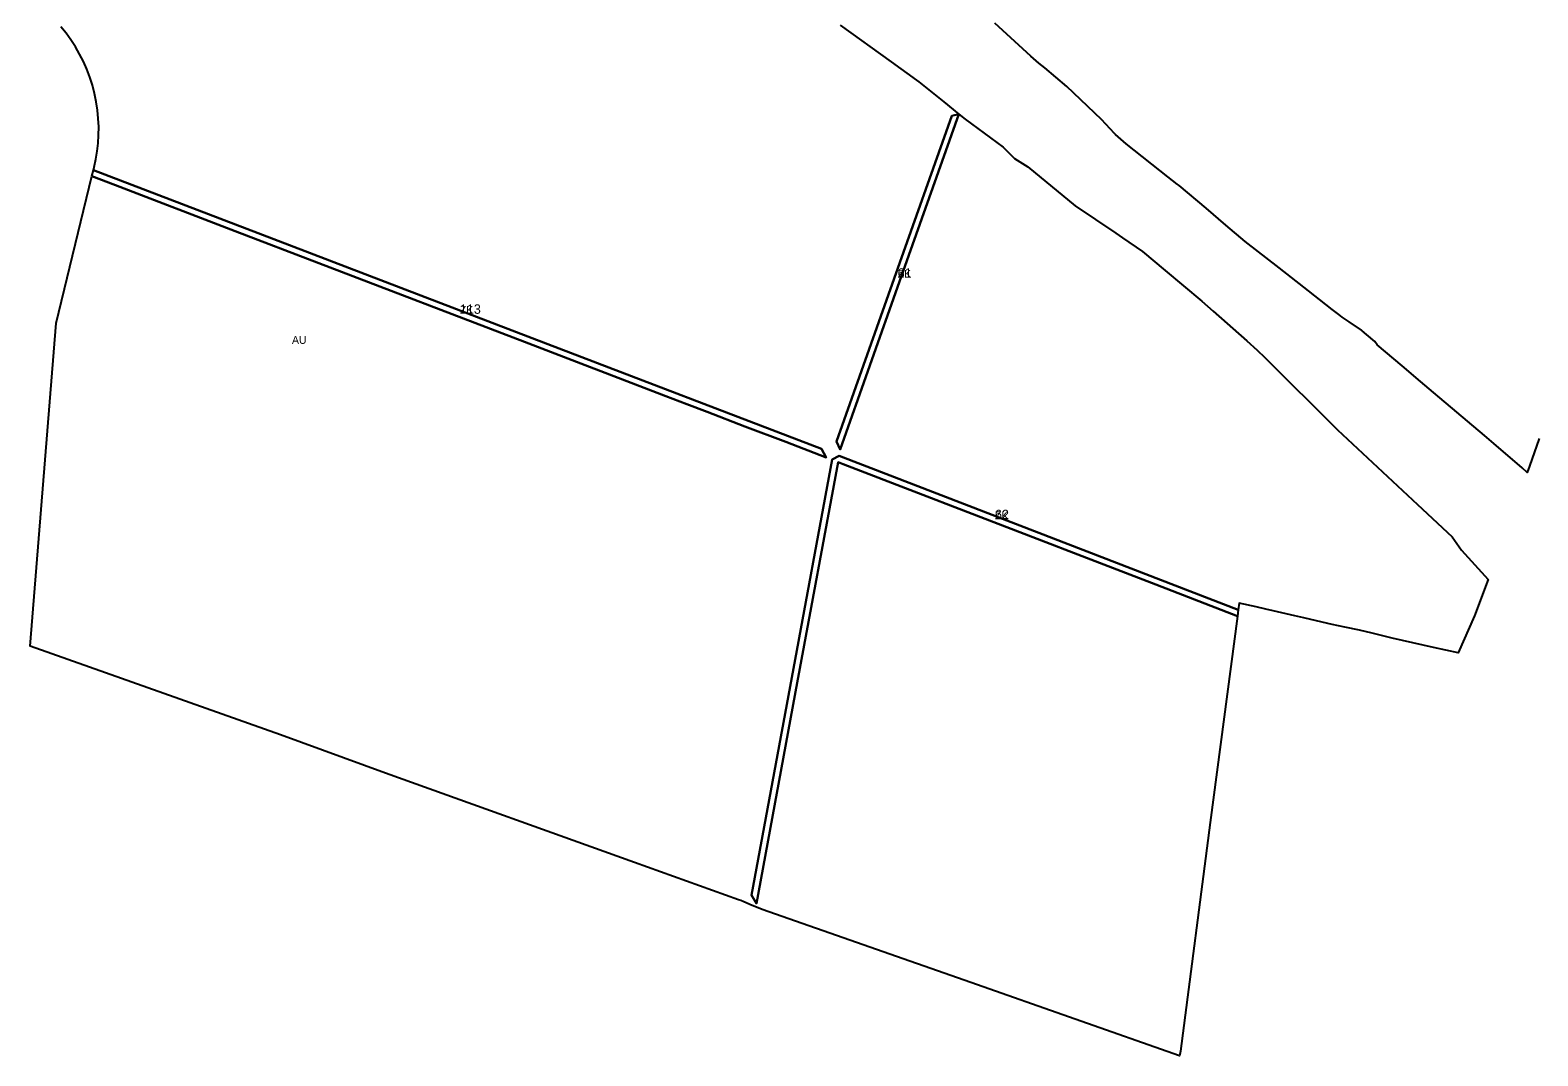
# Model space of a CAD drawing. Extents: x -545779 to -541342, y -1153413 to -1149956.
# Drawn here: x -544795 to -543834, y -1153413 to -1152759 of the extents above; entities that cross this region are included whole.
import ezdxf

# ---------------------------------------------------------------- set-up
doc = ezdxf.new("R2010")
doc.units = 0
for name, color, linetype in [('90710023', 7, 'Continuous'), ('90750013', 7, 'Continuous'), ('ID_navrh', 7, 'Continuous')]:
    doc.layers.add(name, color=color, linetype=linetype)

msp = doc.modelspace()

# ---------------------------------------------------------------- linework, layer by layer
at = {"layer": '90710023'}
for points in [[(-544280.83, -1153021.45), (-544244.07, -1152917.68), (-544207.32, -1152813.93), (-544202.68, -1152812.8), (-544240.52, -1152919.64), (-544278.41, -1153026.55)], [(-544755.518, -1152852.517), (-544754.562, -1152848.599), (-544639.44, -1152892.66), (-544464.89, -1152959.47), (-544290.33, -1153026.28), (-544287.34, -1153031.71), (-544313.08, -1153021.86), (-544339.15, -1153011.88), (-544363.26, -1153002.64), (-544376.19, -1152997.7), (-544389.6, -1152992.56), (-544479.75, -1152958.06), (-544610.94, -1152907.84), (-544664.13, -1152887.48), (-544740.52, -1152858.26)], [(-544228.5, -1153054.38), (-544276.42, -1153035.9), (-544279.74, -1153034.62), (-544305.77, -1153175.27), (-544331.81, -1153315.93), (-544334.88, -1153310.66), (-544309.2, -1153171.88), (-544283.53, -1153033.1), (-544279.06, -1153030.59), (-544151.81, -1153079.68), (-544024.58, -1153128.76), (-544025.12, -1153132.84), (-544077.19, -1153112.75), (-544199.81, -1153065.45)]]:
    msp.add_lwpolyline(points, close=True, dxfattribs=at)
at = {"layer": '90750013'}
for points in [[(-544278.41, -1152756.13), (-544245.81, -1152779.45), (-544229.77, -1152791.13), (-544228.24, -1152792.36), (-544212.41, -1152805.01), (-544202.68, -1152812.8), (-544207.32, -1152813.93), (-544244.07, -1152917.68), (-544280.83, -1153021.45), (-544278.41, -1153026.55), (-544240.52, -1152919.64), (-544202.68, -1152812.8), (-544198.64, -1152816.04), (-544174.44, -1152834.01), (-544167.29, -1152841.09), (-544158.83, -1152846.51), (-544128.48, -1152871.28), (-544102.64, -1152888.66), (-544098.41, -1152891.63), (-544085.71, -1152900.52), (-544071.13, -1152912.54), (-544047.89, -1152932.2), (-544040.66, -1152938.55), (-544019.19, -1152957.42), (-544012.51, -1152963.29), (-544007.74, -1152968.03), (-543961.34, -1153014.15), (-543910.23, -1153061.78), (-543888.14, -1153082.38), (-543882.27, -1153090.72), (-543865.2, -1153109.41), (-543873.93, -1153132.72), (-543884.38, -1153156.23), (-543899.99, -1153152.75), (-543926.42, -1153146.9), (-543938.37, -1153144), (-543939.28, -1153143.78), (-543947.27, -1153141.84), (-543956.62, -1153139.83), (-543964.66, -1153138.11), (-543974.69, -1153135.82), (-543982.84, -1153133.95), (-543988.47, -1153132.65), (-544002.39, -1153129.44), (-544007.07, -1153128.36), (-544013.24, -1153127.02), (-544024.04, -1153124.68), (-544024.58, -1153128.76), (-544151.81, -1153079.68), (-544279.06, -1153030.59), (-544283.53, -1153033.1), (-544309.2, -1153171.88), (-544334.88, -1153310.66), (-544331.81, -1153315.93), (-544305.77, -1153175.27), (-544279.74, -1153034.62), (-544276.42, -1153035.9), (-544228.5, -1153054.38), (-544199.81, -1153065.45), (-544077.19, -1153112.75), (-544025.12, -1153132.84), (-544042.45, -1153264.39), (-544061.43, -1153410.15), (-544061.65, -1153411.16), (-544062.07, -1153413.13), (-544195.15, -1153366.44), (-544328.23, -1153319.76), (-544335.98, -1153316.58), (-544336.47, -1153316.38), (-544339.76, -1153315.03), (-544339.83, -1153315), (-544341.73, -1153314.22), (-544343.25, -1153313.6), (-544409.47, -1153289.86), (-544568.24, -1153232.98), (-544635.19, -1153208.6), (-544757.12, -1153165.33), (-544794.921, -1153151.915), (-544778.35, -1152946.041), (-544755.518, -1152852.517), (-544740.52, -1152858.26), (-544664.13, -1152887.48), (-544610.94, -1152907.84), (-544479.75, -1152958.06), (-544389.6, -1152992.56), (-544376.19, -1152997.7), (-544363.26, -1153002.64), (-544339.15, -1153011.88), (-544313.08, -1153021.86), (-544287.34, -1153031.71), (-544290.33, -1153026.28), (-544464.89, -1152959.47), (-544639.44, -1152892.66), (-544754.562, -1152848.599), (-544754.073, -1152846.597), (-544752.994, -1152841.641), (-544752.158, -1152836.575), (-544751.576, -1152831.416), (-544751.258, -1152826.184), (-544751.213, -1152820.898), (-544751.448, -1152815.579), (-544751.968, -1152810.251), (-544752.773, -1152804.935), (-544753.865, -1152799.654), (-544755.239, -1152794.432), (-544756.892, -1152789.291), (-544758.814, -1152784.253), (-544760.996, -1152779.339), (-544763.426, -1152774.569), (-544766.09, -1152769.96), (-544768.973, -1152765.529), (-544772.057, -1152761.29), (-544775.324, -1152757.255)], [(-543832.69, -1153019.68), (-543838.97, -1153037.19), (-543840.42, -1153041.24), (-543843.66, -1153038.42), (-543861.66, -1153022.76), (-543867.58, -1153017.73), (-543896.02, -1152993.67), (-543900.02, -1152990.29), (-543908.33, -1152983.26), (-543920.04, -1152973.36), (-543935.99, -1152959.87), (-543937.53, -1152957.88), (-543938.8, -1152956.79), (-543945.5, -1152951.03), (-543946.1, -1152950.62), (-543953.84, -1152945.37), (-543956.39, -1152943.64), (-543958.35, -1152942.31), (-543960.52, -1152940.61), (-543964.72, -1152937.33), (-543972.75, -1152931.06), (-543982.78, -1152923.24), (-543998.54, -1152910.94), (-544020.15, -1152894.08), (-544032.47, -1152883.59), (-544045.06, -1152872.85), (-544062.29, -1152858.42), (-544063.52, -1152857.45), (-544069.4, -1152852.8), (-544096.05, -1152831.75), (-544102.77, -1152825.96), (-544103.6, -1152825.24), (-544111.84, -1152816.35), (-544133.84, -1152795.32), (-544147.93, -1152783.46), (-544151.68, -1152780.3), (-544156.94, -1152775.87), (-544179.87, -1152754.91)]]:
    msp.add_lwpolyline(points, dxfattribs=at)

# ---------------------------------------------------------------- texts
at = {"layer": '90710023'}
for rotation, p in [(0, (-544241.755, -1152917.135)), (360, (-544520.939, -1152940.154)), (0, (-544179.73, -1153071.052))]:
    msp.add_text('ZK', height=5, rotation=rotation, dxfattribs=at).set_placement(p)
at = {"layer": '90750013'}
msp.add_text('AU', height=5, rotation=360, dxfattribs=at).set_placement((-544627.97, -1152959.295))
at = {"layer": 'ID_navrh'}
for s, rotation, p in [('61', 360, (-544241.755, -1152917.135)), ('113', 360, (-544520.939, -1152940.154)), ('62', 0, (-544179.73, -1153071.052))]:
    msp.add_text(s, height=6, rotation=rotation, dxfattribs=at).set_placement(p)

doc.saveas('drawing.dxf')
